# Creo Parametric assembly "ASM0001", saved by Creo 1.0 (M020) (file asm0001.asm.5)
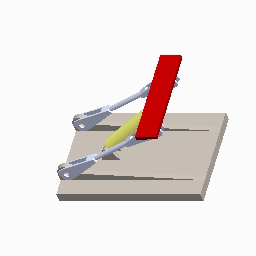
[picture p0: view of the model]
Units: millimeter Newton Second (mmNs); MM, TONNE, SECS

Other parameters: SPRING_LENGTH_UNSTRETCHED

Created from: ASSEMBLAGERELEVAGE.ASM

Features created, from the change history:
  component "SOCLE.PRT"
  component "BRAS.PRT" (7 times)
  datum axis "AA_1"
  datum axis "AA_2"
  datum plane "ADTM1"
  datum axis "AA_3"
  component "SUPPORT.PRT" (3 times)
  component "CORPS_VERIN.PRT"
  component "TIGE_PISTON.PRT" (2 times)
  feature "Ressort 1" (2 times)
  feature "Amortisseur 1" (2 times)
  component "SUPPORTBIS.PRT"
  component "SOCLEBIS"
  component "CORPS_VERIN"
  component "TIGE_PISTON"
  component "SUPPORTBIS"
  component "BRAS" (2 times)

Other named items: ASM_RIGHT, ASM_TOP, ASM_FRONT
